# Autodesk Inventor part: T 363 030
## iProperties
Created: 2005-12
Part Number: T 363 030
Material: 1.0330.5
Document SubType Name: Sheet Metal
Designer: I.Baliuc
Manufacturer: Standard
Standards Organization: Custom
Description: Seitenblech, rechts
Density: 7.84 g/cm^3
Sheet Metal Rule: Standard
Title: Seitenblech, rechts
Company: Mayer & Müller AG Schaltgeräte
Author: T.Messerschmitt
Keywords: 381003
Revision Number: 363030
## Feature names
1. Extrusion1
2. Bezeichnung2 [Tagging]
